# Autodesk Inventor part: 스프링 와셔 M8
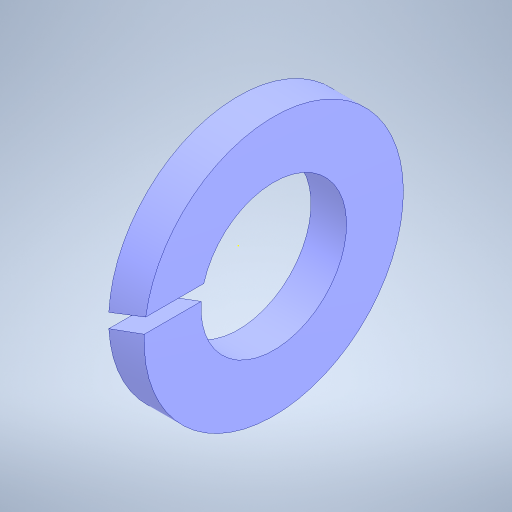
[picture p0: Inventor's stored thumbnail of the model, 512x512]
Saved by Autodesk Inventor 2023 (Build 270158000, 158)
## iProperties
Created: 2025-10
Part Number: 스프링 와셔 M8
Material: 강철, 연강
Description: 스프링 잠금 와셔
Document SubType Name: Modeling
Designer: home
Density: 7.85 g/cm^3
Appearance: 기본값
Author: jhkim
Sending System: Autodesk Inventor 2026
Preprocessor: ST-DEVELOPER v20.1
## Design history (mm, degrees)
sketch "스케치1"
  geometry: 1 further point
  constraints: 1 other
feature "Solid1"
node "솔리드1"
